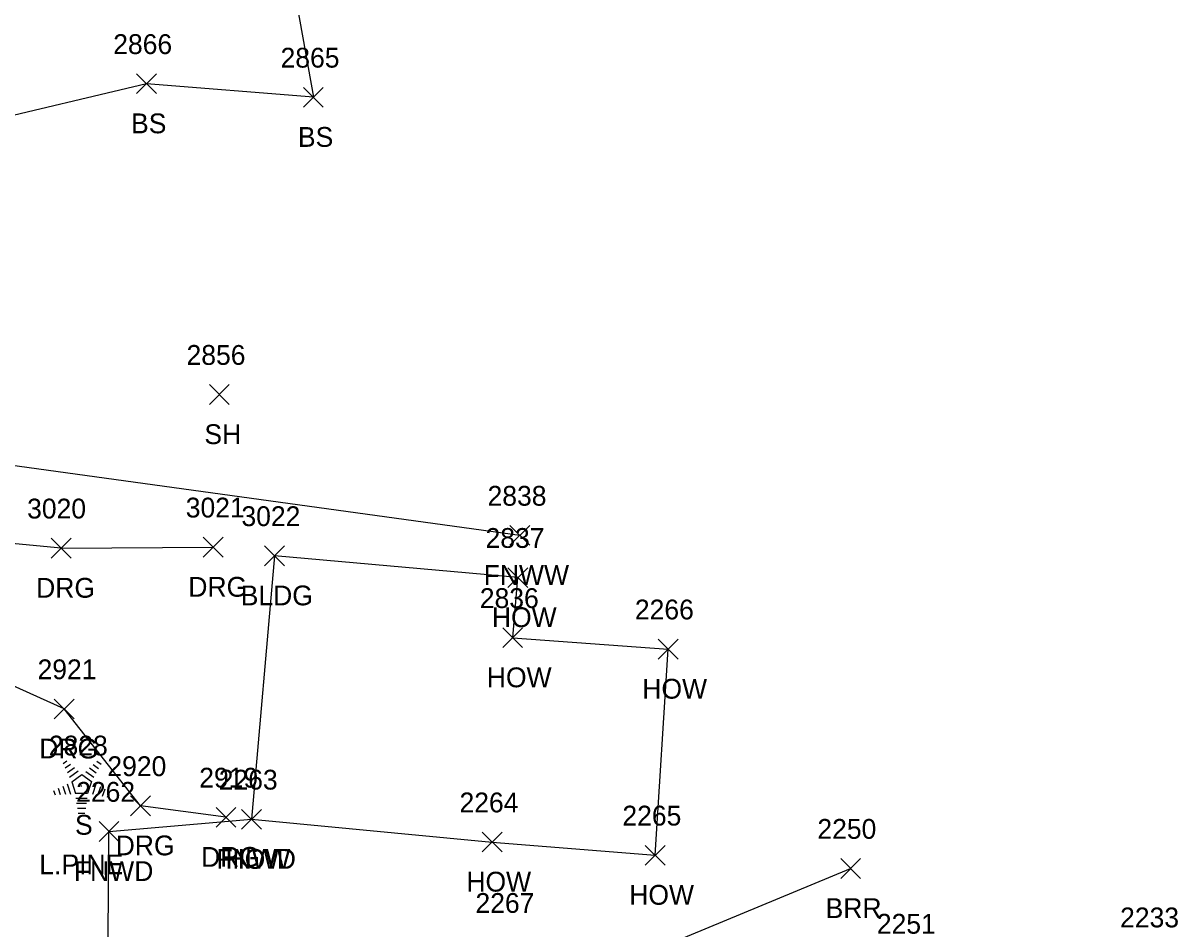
# Model space of a CAD drawing. Extents: x 1609623 to 1616187, y 756677 to 762826.
# Drawn here: x 1610708.8 to 1610825.4, y 761993.3 to 762084.8 of the extents above; entities that cross this region are included whole.
import ezdxf

# ---------------------------------------------------------------- set-up
doc = ezdxf.new("R2010")
doc.units = 0
for name, color, linetype in [('L_A', 7, 'Continuous'), ('L_C', 7, 'Continuous'), ('L_I', 7, 'Continuous'), ('L_TIC', 7, 'Continuous'), ('LABL', 7, 'Continuous'), ('LBC', 7, 'Continuous'), ('LELB', 7, 'Continuous'), ('LFNC', 7, 'Continuous'), ('LTC', 7, 'Continuous'), ('R_A', 7, 'Continuous'), ('R_I', 7, 'Continuous'), ('R_TIC', 7, 'Continuous'), ('RDG', 7, 'Continuous')]:
    doc.layers.add(name, color=color, linetype=linetype)

msp = doc.modelspace()

# ---------------------------------------------------------------- linework, layer by layer
at = {"layer": 'L_TIC'}
for points in [[(1610720.28, 762077.67), (1610722.28, 762079.67)], [(1610722.28, 762077.67), (1610720.28, 762079.67)], [(1610737.12, 762076.3), (1610739.12, 762078.3)], [(1610739.12, 762076.3), (1610737.12, 762078.3)], [(1610727.63, 762046.29), (1610729.63, 762048.29)], [(1610729.63, 762046.29), (1610727.63, 762048.29)], [(1610757.96, 762032.07), (1610759.96, 762034.07)], [(1610759.96, 762032.07), (1610757.96, 762034.07)], [(1610733.2, 762030.01), (1610735.2, 762032.01)], [(1610735.2, 762030.01), (1610733.2, 762032.01)], [(1610757.76, 762027.81), (1610759.76, 762029.81)], [(1610759.76, 762027.81), (1610757.76, 762029.81)], [(1610757.24, 762021.74), (1610759.24, 762023.74)], [(1610759.24, 762021.74), (1610757.24, 762023.74)], [(1610772.93, 762020.59), (1610774.93, 762022.59)], [(1610774.93, 762020.59), (1610772.93, 762022.59)], [(1610730.88, 762003.41), (1610732.88, 762005.41)], [(1610732.88, 762003.41), (1610730.88, 762005.41)], [(1610730.88, 762003.41), (1610732.88, 762005.41)], [(1610732.88, 762003.41), (1610730.88, 762005.41)], [(1610716.49, 762002.18), (1610718.49, 762004.18)], [(1610718.49, 762002.18), (1610716.49, 762004.18)], [(1610755.17, 762001.11), (1610757.17, 762003.11)], [(1610757.17, 762001.11), (1610755.17, 762003.11)], [(1610771.62, 761999.78), (1610773.62, 762001.78)], [(1610773.62, 761999.78), (1610771.62, 762001.78)], [(1610791.34, 761998.44), (1610793.34, 762000.44)], [(1610793.34, 761998.44), (1610791.34, 762000.44)]]:
    msp.add_lwpolyline(points, dxfattribs=at)
at = {"layer": 'LABL'}
msp.add_lwpolyline([(1610822.8, 761990.5), (1610816.37, 761964.31), (1610799.33, 761934.51), (1610779.53, 761924.47), (1610770.7, 761892.35), (1610746.55, 761883.72), (1610721.08, 761880.72), (1610720.51, 761883.61), (1610718.95, 761896.88), (1610711.92, 761905.13), (1610716.12, 761931.04), (1610735.71, 761944.11), (1610756.54, 761960.66), (1610765.19, 761988.18), (1610792.34, 761999.44)], dxfattribs=at)
at = {"layer": 'LBC'}
for points in [[(1610734.2, 762031.01), (1610731.88, 762004.41)], [(1610758.76, 762028.81), (1610734.2, 762031.01)], [(1610758.24, 762022.74), (1610758.76, 762028.81)], [(1610758.24, 762022.74), (1610773.93, 762021.59)], [(1610731.88, 762004.41), (1610756.17, 762002.11), (1610772.62, 762000.78), (1610773.93, 762021.59)]]:
    msp.add_lwpolyline(points, dxfattribs=at)
at = {"layer": 'LELB'}
msp.add_lwpolyline([(1610653.77, 762107.58), (1610676.67, 762106.93), (1610697.29, 762103.95), (1610720.91, 762101.24), (1610733.92, 762100.75), (1610738.12, 762077.3), (1610721.28, 762078.67), (1610704.52, 762074.7), (1610679.87, 762081.92)], dxfattribs=at)
at = {"layer": 'LFNC'}
for points in [[(1610758.96, 762033.07), (1610692.81, 762042.19), (1610667.3, 762045.45), (1610629.86, 762049.8), (1610629.79, 762066.7), (1610630.31, 762076.22)], [(1610717.94, 761938.34), (1610717.18, 761953.82), (1610717.49, 762003.18), (1610731.88, 762004.41)]]:
    msp.add_lwpolyline(points, dxfattribs=at)
at = {"layer": 'LTC'}
for p, q in [((1610712.87, 762010.05), (1610713.23, 762010.31)), ((1610713.08, 762009.59), (1610713.61, 762009.97)), ((1610713.29, 762009.12), (1610714, 762009.63)), ((1610713.5, 762008.66), (1610714.38, 762009.3)), ((1610715.16, 762009.25), (1610715.97, 762008.66)), ((1610715.53, 762009.6), (1610716.21, 762009.1)), ((1610715.9, 762009.95), (1610716.45, 762009.55)), ((1610716.27, 762010.29), (1610716.69, 762009.99)), ((1610713.73, 762008.2), (1610714.74, 762008.94)), ((1610713.73, 762008.2), (1610714.11, 762007.01)), ((1610714.74, 762008.94), (1610715.73, 762008.21)), ((1610715.73, 762008.21), (1610715.34, 762007.01)), ((1610711.9, 762007.33), (1610712.06, 762006.87)), ((1610712.36, 762007.55), (1610712.57, 762006.9)), ((1610712.82, 762007.77), (1610713.09, 762006.93)), ((1610713.27, 762007.98), (1610713.6, 762006.96)), ((1610715.34, 762007.01), (1610714.11, 762007.01)), ((1610716.17, 762007.94), (1610715.83, 762006.9)), ((1610716.62, 762007.69), (1610716.33, 762006.81)), ((1610717.06, 762007.44), (1610716.82, 762006.71)), ((1610717.51, 762007.19), (1610717.32, 762006.62)), ((1610715.3, 762006.51), (1610714.16, 762006.51)), ((1610715.22, 762006.01), (1610714.23, 762006.01)), ((1610715.14, 762005.51), (1610714.31, 762005.51)), ((1610715.05, 762005.01), (1610714.38, 762005.01))]:
    msp.add_line(p, q, dxfattribs=at)
at = {"layer": 'R_TIC'}
for points in [[(1610711.66, 762030.78), (1610713.66, 762032.78)], [(1610713.66, 762030.78), (1610711.66, 762032.78)], [(1610727.01, 762030.88), (1610729.01, 762032.88)], [(1610729.01, 762030.88), (1610727.01, 762032.88)], [(1610711.97, 762014.55), (1610713.97, 762016.55)], [(1610713.97, 762014.55), (1610711.97, 762016.55)], [(1610719.68, 762004.77), (1610721.68, 762006.77)], [(1610721.68, 762004.77), (1610719.68, 762006.77)], [(1610728.3, 762003.61), (1610730.3, 762005.61)], [(1610730.3, 762003.61), (1610728.3, 762005.61)]]:
    msp.add_lwpolyline(points, dxfattribs=at)
at = {"layer": 'RDG'}
for points in [[(1610729.3, 762004.61), (1610720.68, 762005.77), (1610712.97, 762015.55), (1610702.28, 762020.37), (1610678.72, 762026.38), (1610644.62, 762033.17), (1610626.03, 762036.9), (1610619.16, 762034.17)], [(1610712.66, 762031.78), (1610695.29, 762033.44)], [(1610712.66, 762031.78), (1610728.01, 762031.88)]]:
    msp.add_lwpolyline(points, dxfattribs=at)

# ---------------------------------------------------------------- texts
at = {"layer": 'L_A'}
for s, p in [('BS', (1610719.72, 762073.67)), ('BS', (1610736.56, 762072.3)), ('SH', (1610727.12, 762042.29)), ('FNWW', (1610755.31, 762028.07)), ('BLDG', (1610730.79, 762026.01)), ('HOW', (1610756.14, 762023.81)), ('HOW', (1610755.63, 762017.74)), ('HOW', (1610771.32, 762016.59)), ('S', (1610714.06, 762002.85)), ('FNWD', (1610728.34, 761999.41)), ('HOW', (1610729.26, 761999.41)), ('FNWD', (1610713.95, 761998.18)), ('HOW', (1610753.56, 761997.11)), ('HOW', (1610770, 761995.78)), ('BRR', (1610789.82, 761994.44))]:
    msp.add_text(s, height=2, dxfattribs=at).set_placement(p)
at = {"layer": 'L_C'}
msp.add_text('L.PINE', height=2, dxfattribs=at).set_placement((1610710.46, 761998.85))
at = {"layer": 'L_I'}
for s, p in [('2866', (1610717.92, 762081.67)), ('2865', (1610734.81, 762080.3)), ('2856', (1610725.32, 762050.29)), ('2838', (1610755.7, 762036.07)), ('3022', (1610730.86, 762034.01)), ('2837', (1610755.5, 762031.81)), ('2836', (1610754.92, 762025.74)), ('2266', (1610770.57, 762024.59)), ('2828', (1610711.42, 762010.85)), ('2263', (1610728.57, 762007.41)), ('2263', (1610728.57, 762007.41)), ('2262', (1610714.18, 762006.18)), ('2264', (1610752.87, 762005.11)), ('2265', (1610769.31, 762003.78)), ('2250', (1610788.99, 762002.44)), ('2267', (1610754.48, 761994.96)), ('2233', (1610819.54, 761993.5)), ('2251', (1610794.99, 761992.86))]:
    msp.add_text(s, height=2, dxfattribs=at).set_placement(p)
at = {"layer": 'LTC'}
msp.add_text('.', height=1.04, rotation=270, dxfattribs=at).set_placement((1610714.62, 762007.95))
at = {"layer": 'R_A'}
for p in [(1610710.14, 762026.78), (1610725.5, 762026.88), (1610710.46, 762010.55), (1610718.17, 762000.77), (1610726.79, 761999.61)]:
    msp.add_text('DRG', height=2, dxfattribs=at).set_placement(p)
at = {"layer": 'R_I'}
for s, p in [('3020', (1610709.23, 762034.78)), ('3021', (1610725.24, 762034.88)), ('2921', (1610710.28, 762018.55)), ('2920', (1610717.33, 762008.77)), ('2919', (1610726.6, 762007.61))]:
    msp.add_text(s, height=2, dxfattribs=at).set_placement(p)

doc.saveas('drawing.dxf')
